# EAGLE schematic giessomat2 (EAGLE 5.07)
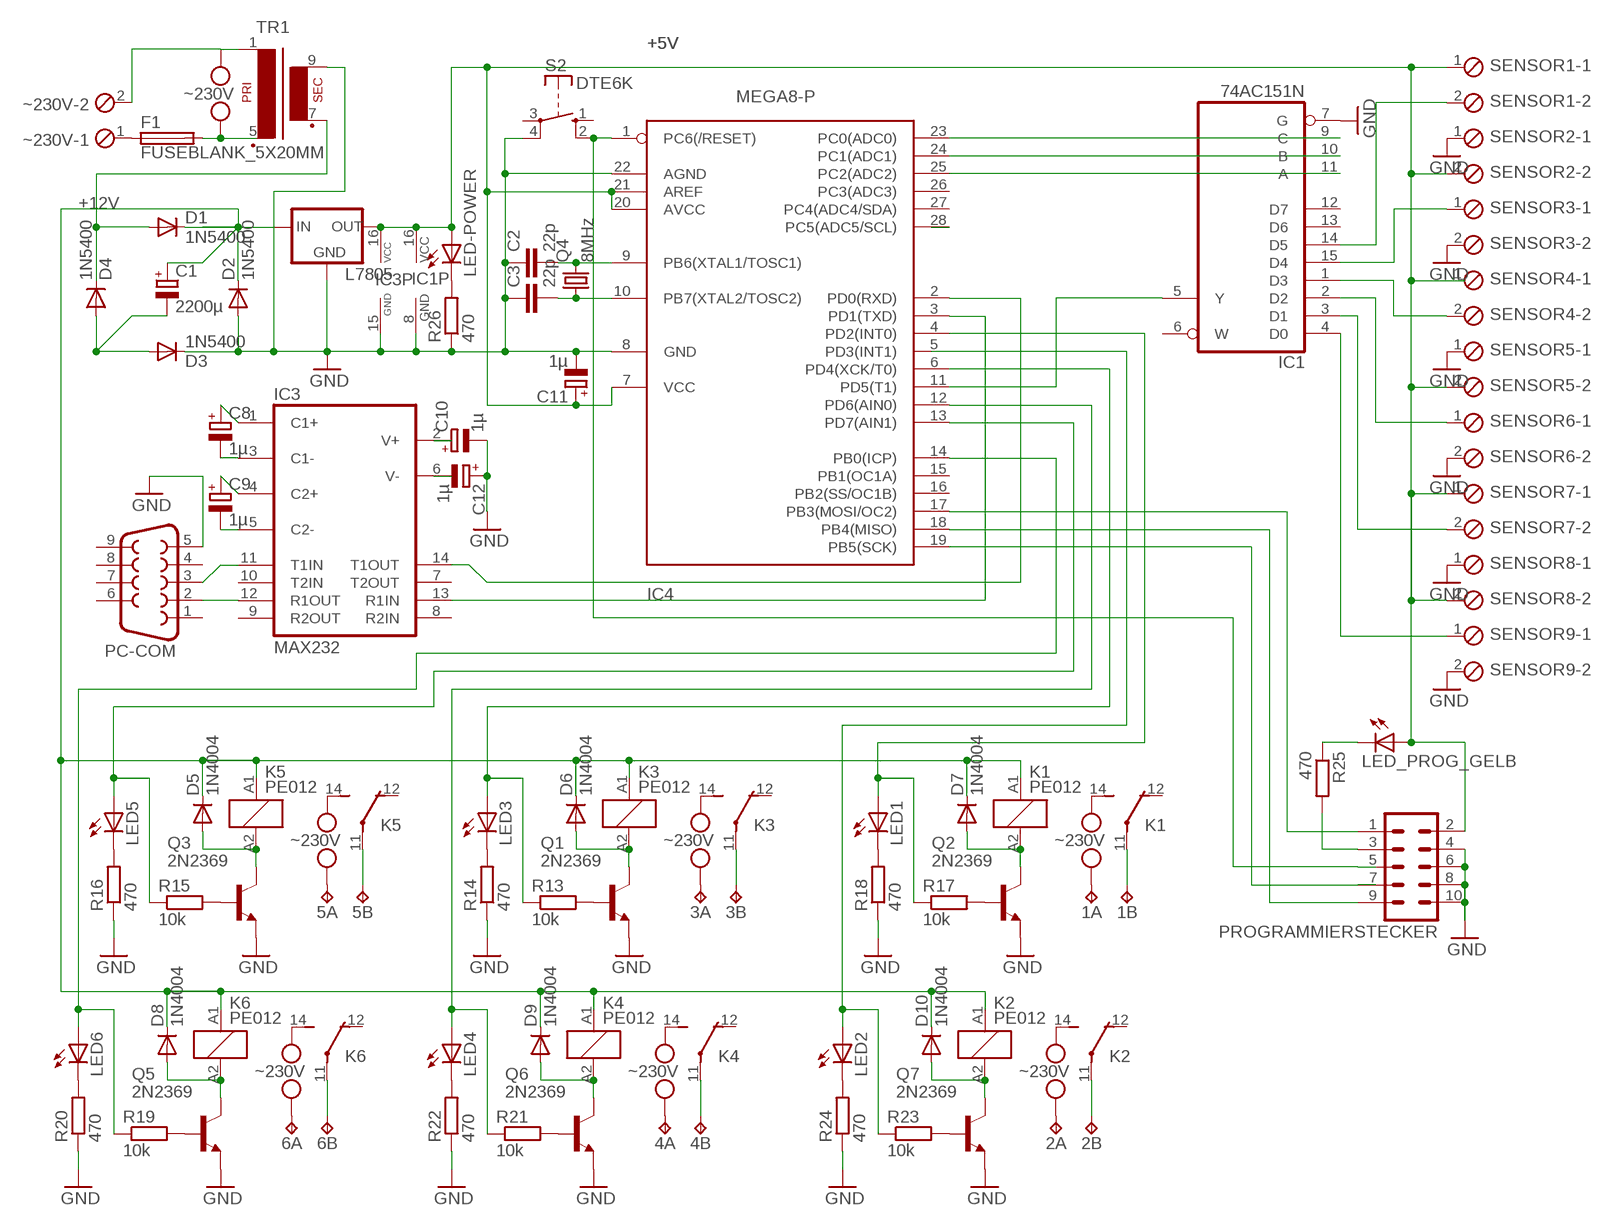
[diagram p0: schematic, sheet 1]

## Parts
1  TP2P2-38-20  [P2-38-20]
2  TP2P2-38-20  [P2-38-20]
3  TP2P2-38-20  [P2-38-20]
4  TP2P2-38-20  [P2-38-20]
5  TP2P2-38-20  [P2-38-20]
6  TP2P2-38-20  [P2-38-20]
C1  2200µ  CPOL-EUE5-8.5  [E5-8,5]
C2  22p  C-EU025-025X050  [C025-025X050]
C3  22p  C-EU025-025X050  [C025-025X050]
C8  1µ  CPOL-EUE1.8-4  [E1,8-4]
C9  1µ  CPOL-EUE1.8-4  [E1,8-4]
C10  1µ  CPOL-EUE1.8-4  [E1,8-4]
C11  1µ  CPOL-EUE1.8-4  [E1,8-4]
C12  1µ  CPOL-EUE1.8-4  [E1,8-4]
D1  1N5400  [DO201-15]
D2  1N5400  [DO201-15]
D3  1N5400  [DO201-15]
D4  1N5400  [DO201-15]
D5  1N4004  [DO41-10]
D6  1N4004  [DO41-10]
D7  1N4004  [DO41-10]
D8  1N4004  [DO41-10]
D9  1N4004  [DO41-10]
D10  1N4004  [DO41-10]
F1  FUSEBLANK_5X20MM  [FUSE_HOLDER_5X20MM]
IC1  74AC151N  [DIL16]
IC3  MAX232  [DIL16]
IC4  MEGA8-P  [DIL28-3]
K1  PE012  [PE]
K2  PE012  [PE]
K3  PE012  [PE]
K4  PE012  [PE]
K5  PE012  [PE]
K6  PE012  [PE]
L7805  78XXS  [78XXS]
LED1  LED5MM  [LED5MM]
LED2  LED5MM  [LED5MM]
LED3  LED5MM  [LED5MM]
LED4  LED5MM  [LED5MM]
LED5  LED5MM  [LED5MM]
LED6  LED5MM  [LED5MM]
LED-POWER  LED5MM  [LED5MM]
LED_PROG_GELB  LED5MM  [LED5MM]
PC-COM  F09V  [F09V]
PROGRAMMIERSTECKER  MA05-2  [MA05-2]
Q1  2N2369  [TO18]
Q2  2N2369  [TO18]
Q3  2N2369  [TO18]
Q4  8MHz  CRYTALHC49U70  [HC49U70]
Q5  2N2369  [TO18]
Q6  2N2369  [TO18]
Q7  2N2369  [TO18]
R13  10k  R-EU_0204/7  [0204/7]
R14  470  R-EU_0204/7  [0204/7]
R15  10k  R-EU_0204/7  [0204/7]
R16  470  R-EU_0204/7  [0204/7]
R17  10k  R-EU_0204/7  [0204/7]
R18  470  R-EU_0204/7  [0204/7]
R19  10k  R-EU_0204/7  [0204/7]
R20  470  R-EU_0204/7  [0204/7]
R21  10k  R-EU_0204/7  [0204/7]
R22  470  R-EU_0204/7  [0204/7]
R23  10k  R-EU_0204/7  [0204/7]
R24  470  R-EU_0204/7  [0204/7]
R25  470  R-EU_0204/7  [0204/7]
R26  470  R-EU_0204/7  [0204/7]
S2  DTE6K  [DTE6K]
SENSOR1  MPT2  [2POL254]
SENSOR2  MPT2  [2POL254]
SENSOR3  MPT2  [2POL254]
SENSOR4  MPT2  [2POL254]
SENSOR5  MPT2  [2POL254]
SENSOR6  MPT2  [2POL254]
SENSOR7  MPT2  [2POL254]
SENSOR8  MPT2  [2POL254]
SENSOR9  MPT2  [2POL254]
TR1  EI30-1  [EI30-1]
~230V  MPT2  [2POL254]

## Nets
+5V: C11.+ IC1.16(VCC) IC3.16(VCC) IC4.7(VCC) IC4.20(AVCC) IC4.21(AREF) L7805.OUT LED-POWER.A LED_PROG_GELB.A PROGRAMMIERSTECKER.2 SENSOR1.1 SENSOR2.2 SENSOR5.2 SENSOR7.1 SENSOR8.2
+12V: C1.+ D1.C D2.C D5.C D6.C D7.C D8.C D9.C D10.C K1.A1 K2.A1 K3.A1 K4.A1 K5.A1 K6.A1 L7805.IN
GND: C2.1 C3.1 C10.- C11.- C12.+ D2.A D3.C IC1.7(G) IC1.8(GND) IC4.8(GND) IC4.22(AGND) L7805.GND PC-COM.5 PROGRAMMIERSTECKER.4 PROGRAMMIERSTECKER.6 PROGRAMMIERSTECKER.8 PROGRAMMIERSTECKER.10 Q1.1(E) Q2.1(E) Q3.1(E) Q5.1(E) Q6.1(E) Q7.1(E) R14.1 R16.1 R18.1 R20.1 R22.1 R24.1 R26.1 S2.4(P) SENSOR2.1 SENSOR3.2 SENSOR5.1 SENSOR6.2 SENSOR8.1 SENSOR9.2 TR1.9
N$1: IC3.13(R1IN) IC4.3(PD1(TXD))
N$2: F1.1 ~230V.1
N$3: LED-POWER.K(C) R26.2
N$4: Q3.2(B) R15.2
N$5: LED2.A R23.1
N$6: D5.A K5.A2 Q3.3(C)
N$7: IC4.4(PD2(INT0)) LED1.A R17.1
N$8: C1.- D3.A D4.A
N$9: PROGRAMMIERSTECKER.7
N$10: IC1.9(C)
N$11: IC1.10(B)
N$12: C3.2 IC4.10(PB7(XTAL2/TOSC2)) Q4.1
N$13: IC1.11(A)
N$14: IC1.14(D5) SENSOR1.2
N$15: C2.2 IC4.9(PB6(XTAL1/TOSC1)) Q4.2
N$16: LED3.K(C) R14.2
N$17: LED6.K(C) R20.2
N$18: 3.2 K3.11(2:P)
N$19: IC4.12(PD6(AIN0)) LED4.A R21.1
N$20: D6.A K3.A2 Q1.3(C)
N$21: LED5.K(C) R16.2
N$22: IC1.15(D4) SENSOR3.1
N$23: Q1.2(B) R13.2
N$24: LED1.K(C) R18.2
N$25: 5.2 K5.11(2:P)
N$26: IC3.15(GND)
N$27: 1.2 K1.11(2:P)
N$28: D7.A K1.A2 Q2.3(C)
N$29: Q2.2(B) R17.2
N$30: 6.2 K6.11(2:P)
N$31: IC4.28(PC5(ADC5/SCL))
N$32: IC1.1(D3) SENSOR4.2
N$33: IC4.6(PD4(XCK/T0)) LED3.A R13.1
N$34: IC1.2(D2) SENSOR6.1
N$35: IC1.3(D1) SENSOR7.2
N$36: D8.A K6.A2 Q5.3(C)
N$37: Q5.2(B) R19.2
N$38: LED4.K(C) R22.2
N$39: 4.2 K4.11(2:P)
N$40: IC1.5(Y) IC4.11(PD5(T1))
N$41: D9.A K4.A2 Q6.3(C)
N$42: Q6.2(B) R21.2
N$43: LED2.K(C) R24.2
N$44: 2.2 K2.11(2:P)
N$45: PROGRAMMIERSTECKER.9
N$46: C10.+ IC3.2(V+)
N$47: IC1.4(D0) SENSOR9.1
N$48: LED_PROG_GELB.K(C) R25.1
N$49: PROGRAMMIERSTECKER.3 R25.2
N$50: D10.A K2.A2 Q7.3(C)
N$51: C8.+ IC3.1(C1+)
N$52: Q7.2(B) R23.2
N$53: IC4.13(PD7(AIN1)) LED5.A R15.1
N$54: PROGRAMMIERSTECKER.1
N$55: IC4.14(PB0(ICP)) LED6.A R19.1
N$57: C8.- IC3.3(C1-)
N$58: C9.+ IC3.4(C2+)
N$59: C12.- IC3.6(V-)
N$61: IC3.14(T1OUT) IC4.2(PD0(RXD))
N$62: IC3.12(R1OUT) PC-COM.2
N$63: IC3.11(T1IN) PC-COM.3
N$64: C9.- IC3.5(C2-)
N$66: D1.A D4.C TR1.7
RESET: IC4.1(PC6(/RESET)) PROGRAMMIERSTECKER.5 S2.2(S)
VPP: K1.14(2:S) K2.14(2:S) K3.14(2:S) K4.14(2:S) K5.14(2:S) K6.14(2:S) TR1.1 ~230V.2
VSS: 1.1 2.1 3.1 4.1 5.1 6.1 F1.2 TR1.5 ; supply symbol labelled ~230V
Unconnected: IC1.6(W) IC1.12(D7) IC1.13(D6) IC3.7(T2OUT) IC3.8(R2IN) IC3.9(R2OUT) IC3.10(T2IN) IC4.5(PD3(INT1)) IC4.15(PB1(OC1A)) IC4.16(PB2(SS/OC1B)) IC4.17(PB3(MOSI/OC2)) IC4.18(PB4(MISO)) IC4.19(PB5(SCK)) IC4.23(PC0(ADC0)) IC4.24(PC1(ADC1)) IC4.25(PC2(ADC2)) IC4.26(PC3(ADC3)) IC4.27(PC4(ADC4/SDA)) K1.12(2:O) K2.12(2:O) K3.12(2:O) K4.12(2:O) K5.12(2:O) K6.12(2:O) PC-COM.1 PC-COM.4 PC-COM.6 PC-COM.7 PC-COM.8 PC-COM.9 S2.1(S) S2.3(P) SENSOR4.1

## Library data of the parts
1-6 = testpad:TP2
C1 C8-C12 = rcl:CPOL-EU: POLARIZED CAPACITOR, European symbol
C2 C3 = rcl:C-EU: CAPACITOR, European symbol
D1-D4 = diode:1N5400: DIODE
D5-D10 = diode:1N4004: DIODE
F1 = fuse:FUSE: Fuse
IC1 = 74xx-eu:74*151: Data SELECTOR/MULTIPLEXER
IC3 = maxim:MAX232: RS232 TRANSEIVER
IC4 = atmel:MEGA8-P: MICROCONTROLLER 8 Kbytes FLASH 1 kbytes SRAM 512 bytes EEPROM USART 4-channel 10 bit ADC 2-channel 8 bit ADC Source: avr.lbr
K1-K6 = relay:PE*: Miniature PCB Relay 1 pole 5 A SCHRACK Source: http://www.schrack.com/.. 5807.pdf Miniature PCB Relay bistable 1pole 5 A, polarized bistable version Source: http://www.schrack.com/.. 5808.pdf
L7805 = v-reg:78XXS: VOLTAGE REGULATOR
LED1-LED6 LED-POWER LED_PROG_GELB = led:LED: LED
PC-COM = con-subd:F09: SUB-D
PROGRAMMIERSTECKER = con-lstb:MA05-2: PIN HEADER
Q1-Q3 Q5-Q7 = transistor-npn:2N2369*: NPN Transistor
Q4 = crystal:CRYTAL: CRYSTAL
R13-R26 = rcl:R-EU_: RESISTOR, European symbol
S2 = switch-misc:DT: ITT SWITCH
SENSOR1-SENSOR9 ~230V = con-phoenix-254:MPT2: PHOENIX CONNECTOR
TR1 = trafo:EI30-1: TRANSFORMER 1 primary winding, 1 secondary winding ERA

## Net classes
0 230V: width 0.013 mm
